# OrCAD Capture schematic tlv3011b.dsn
size A
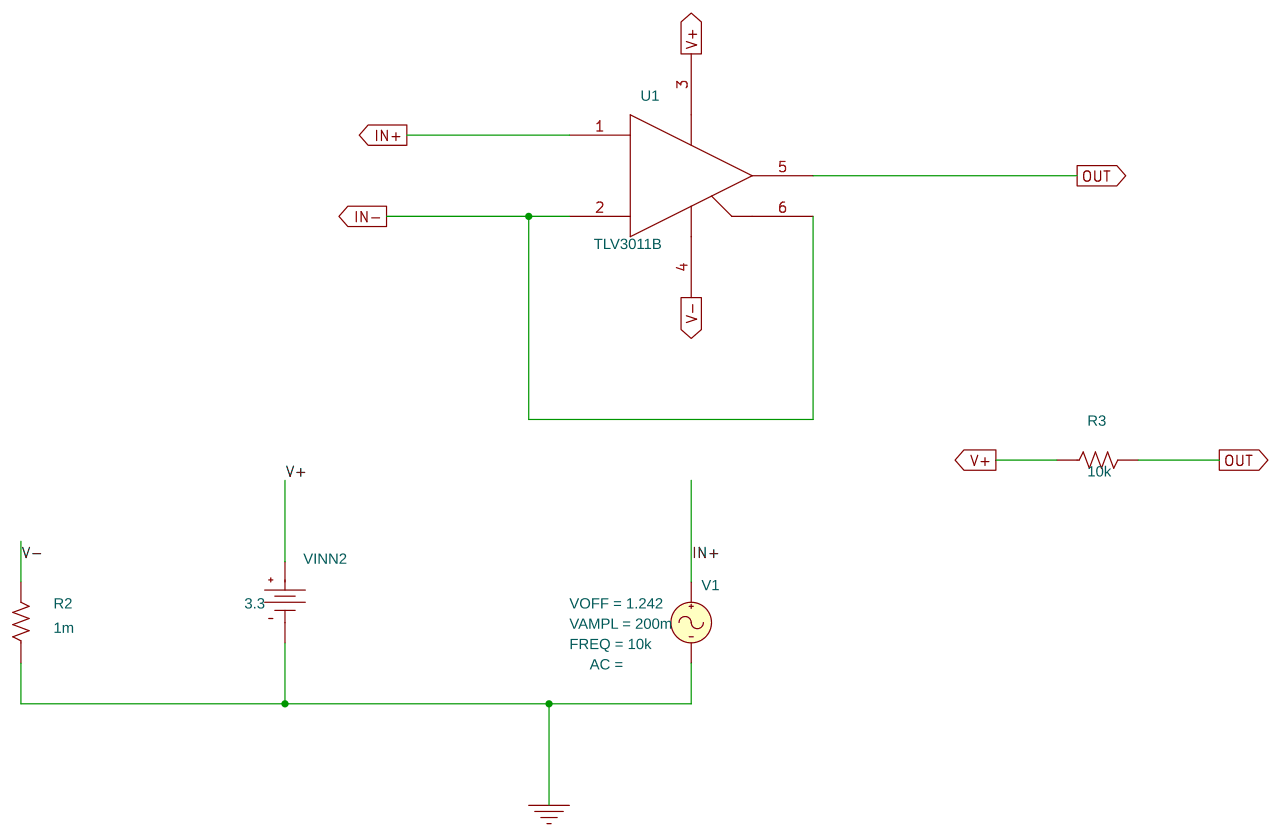
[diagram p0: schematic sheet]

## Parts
R2  1m  [AXRC05]
R3  10k  [AXRC05]
U1  TLV3011B
V1  VSIN
VINN2  VDC

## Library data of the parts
R2 R3 = R
U1 = TLV3011B
V1 = VSIN: FREQ: 10k; VAMPL: 200m; VOFF: 1.242
VINN2 = VDC: DC: 3.3

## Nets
0: R2.1 V1.2(-) VINN2.1(-)
IN+: U1.1(IN+) V1.1(+)
IN-: U1.2(IN-) U1.6(REF)
OUT: R3.2 U1.5(OUT)
V+: R3.1 U1.3(V+) VINN2.0(+)
V-: R2.2 U1.4(V-)
